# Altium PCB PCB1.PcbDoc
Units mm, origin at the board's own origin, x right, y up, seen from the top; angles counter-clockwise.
Board outline 68.2 x 35.94 mm, 2 copper layers (Top Layer, Bottom Layer); 89 components, 54 nets, 273 pads, 72 vias.
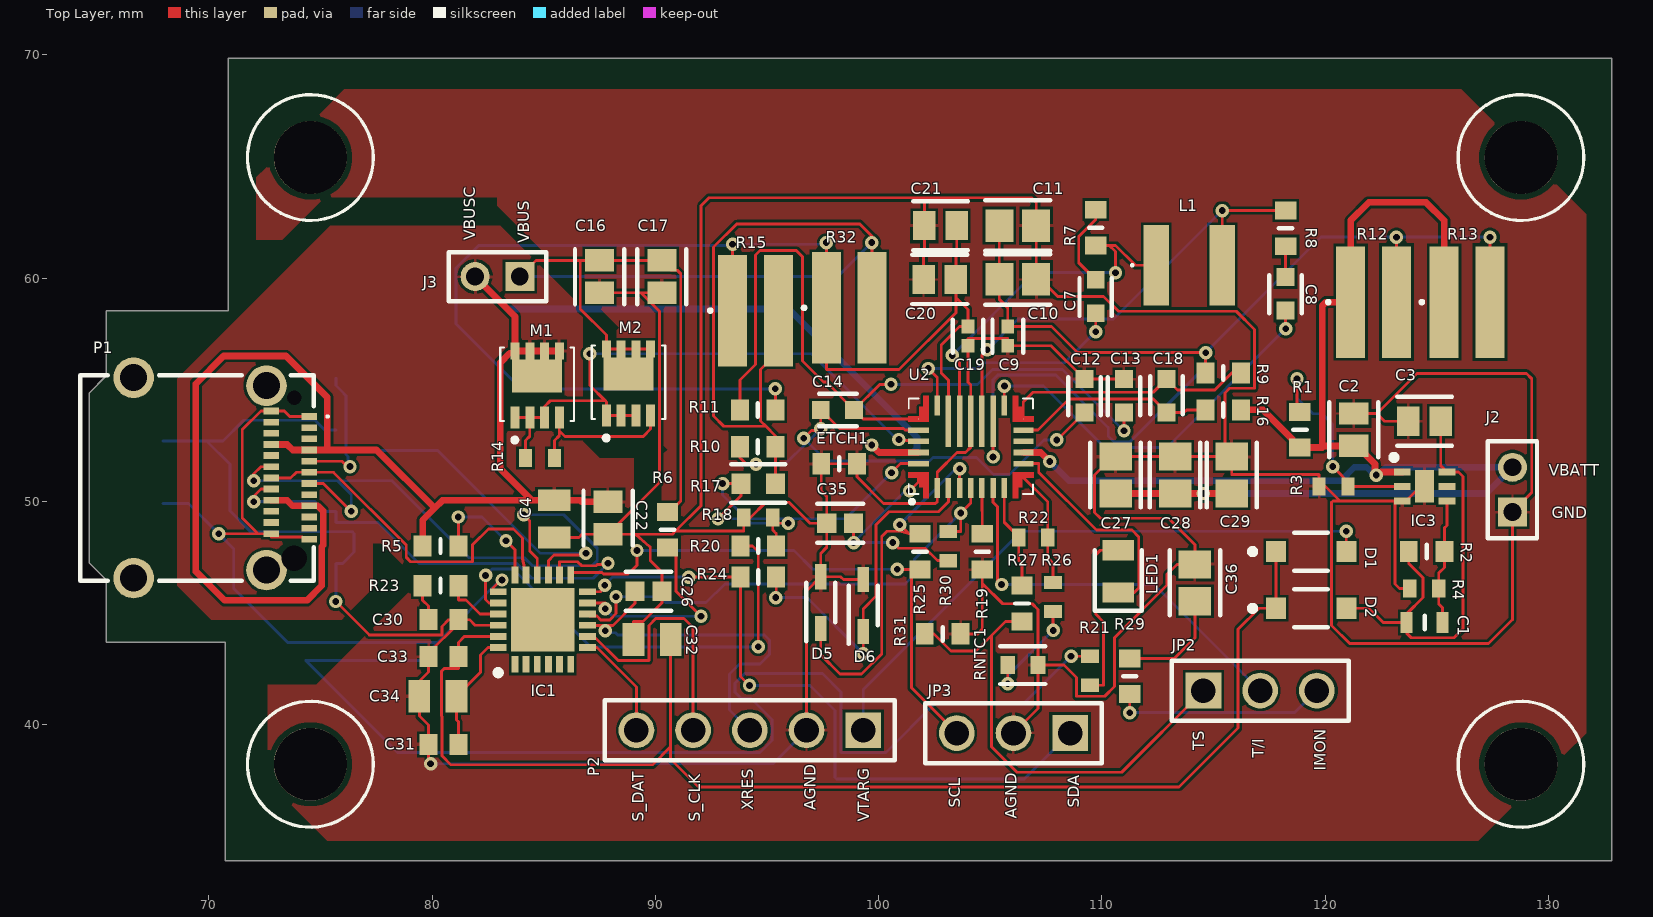
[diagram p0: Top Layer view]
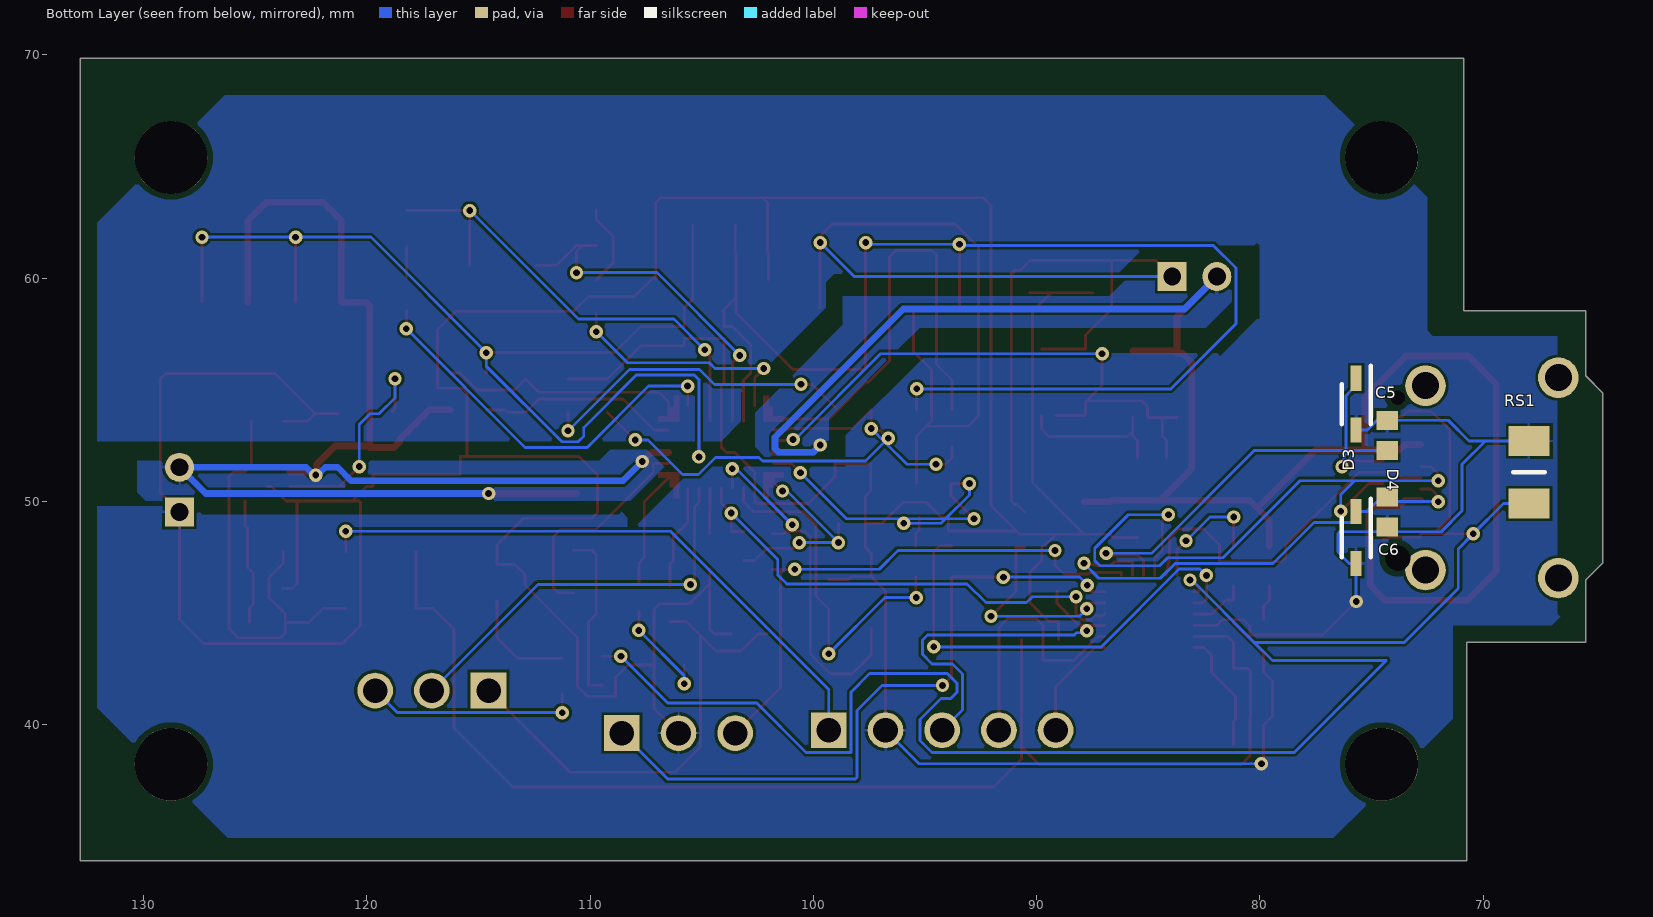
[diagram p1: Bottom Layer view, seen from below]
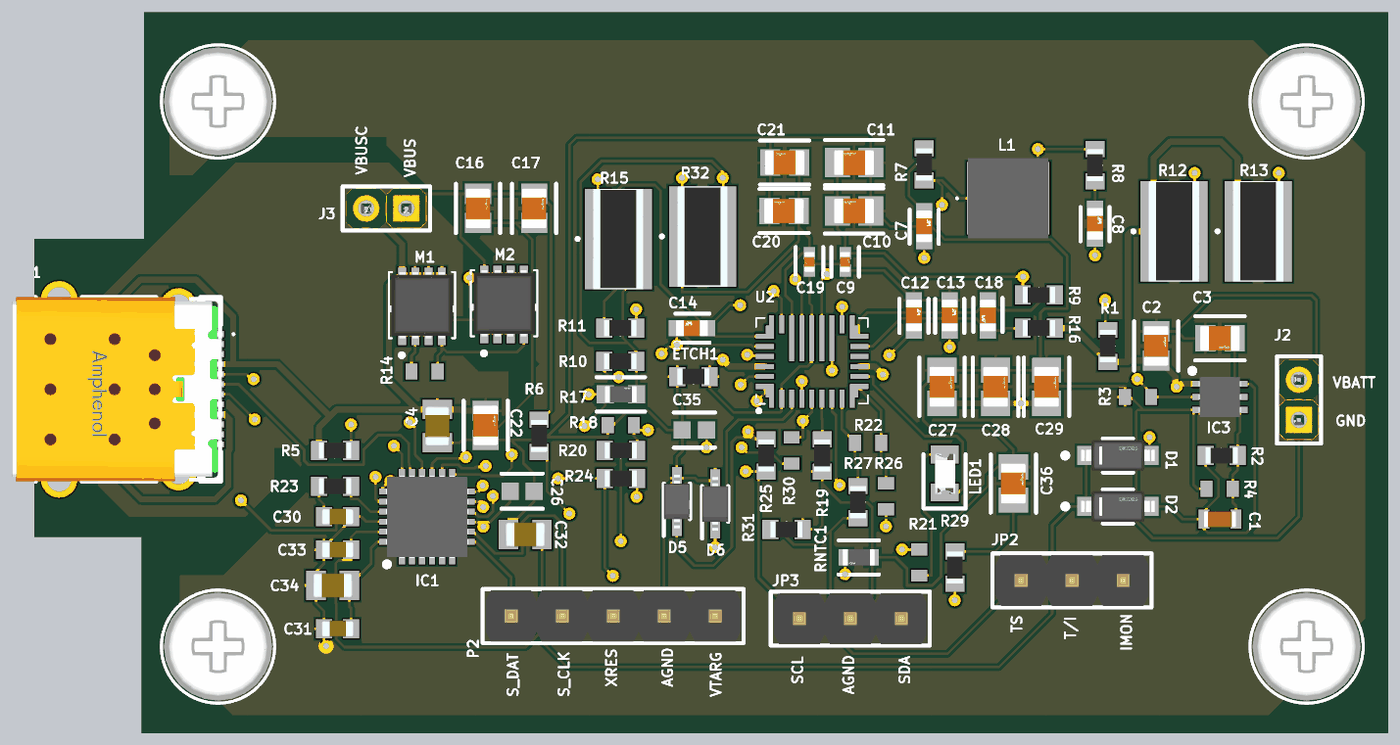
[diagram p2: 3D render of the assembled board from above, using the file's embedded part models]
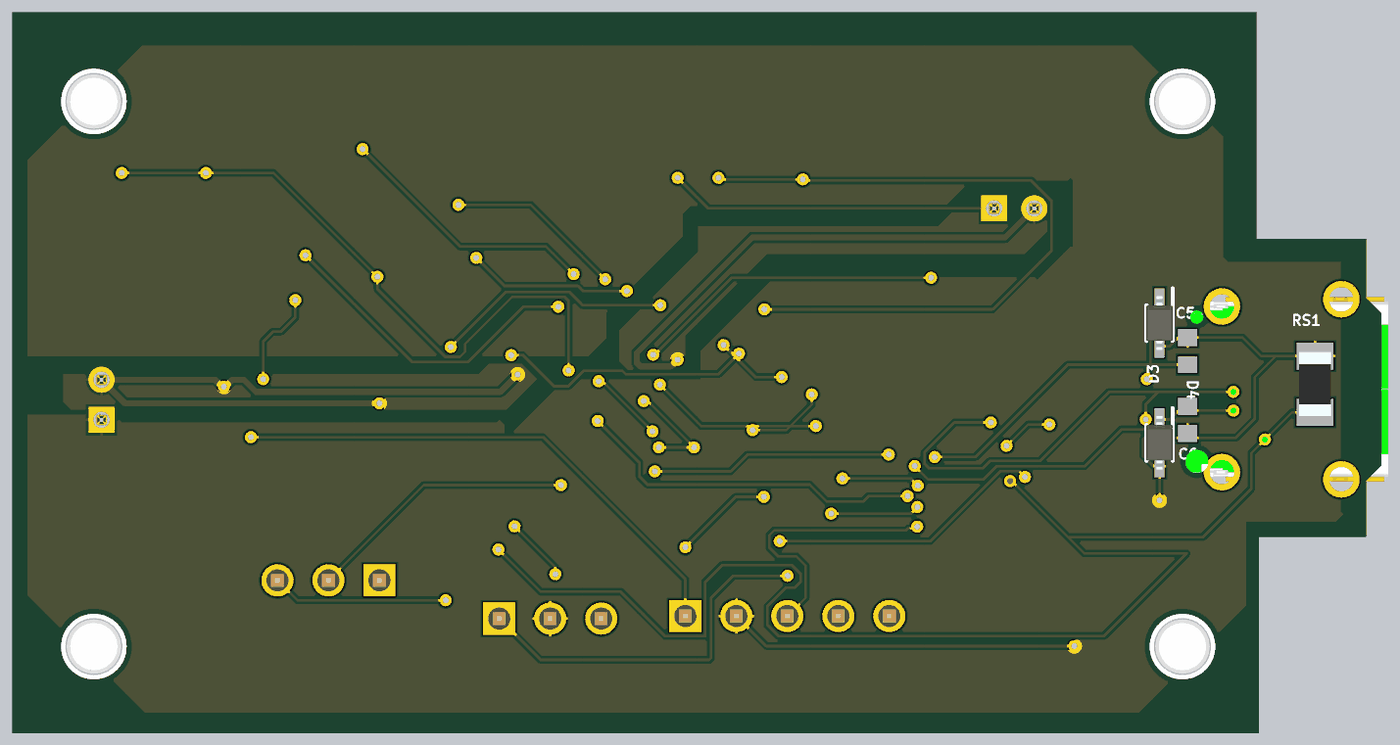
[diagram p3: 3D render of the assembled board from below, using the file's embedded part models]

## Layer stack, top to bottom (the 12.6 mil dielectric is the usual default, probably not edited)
Top Solder: solder mask 0.0102, Solder Resist, Dk 3.5
Top Layer: signal copper 0.035
Dielectric 1: dielectric 0.32, FR-4, Dk 4.8
Bottom Layer: signal copper 0.035
Bottom Solder: solder mask 0.0102, Solder Resist, Dk 3.5

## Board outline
64.643,47.244 65.405,46.482 65.405,43.688 70.739,43.688 70.739,33.909 132.842,33.909 132.842,69.85 70.866,69.85 70.866,58.547 65.405,58.547 65.405,55.626 64.643,54.864

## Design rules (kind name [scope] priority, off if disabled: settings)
BoardOutlineClearance [All] p1: gap=0.2 ignorepadtopadclearanceinfootprint=FALSE
Clearance [All] p1: gap=0.127 ignorepadtopadclearanceinfootprint=FALSE except(0.25: Arc-Hole Track-Hole SMDPad-Hole THPad-Hole Via-Hole Fill-Hole Poly-Hole Region-Hole Text-Hole)
ComponentClearance [All] p1: gap=0.127 collisioncheckmode=3 verticalgap=0.127 showdistances=TRUE
DiffPairsRouting [All] p1: maxlimit=0.254 minlimit=0.127 mostfreqgap=0.127 toplayer_minwidth=0.127 toplayer_maxwidth=25.4 toplayer_prefwidth=0.127 bottomlayer_minwidth=0.127 bottomlayer_maxwidth=25.4 bottomlayer_prefwidth=0.127 maxuncoupledlength=12.7
Height [All] p1: minheight=0 maxheight=1816.048 prefheight=12.7
HoleSize [All] p1: absolutevalues=TRUE maxlimit=6.3 minlimit=0.3 maxpercent=80.000 minpercent=20.000
HoleToHoleClearance [All] p1: gap=0.25 allowstackedmicrovias=FALSE
MinimumAnnularRing [All] p1: minimumring=0.076
MinimumSolderMaskSliver [All] p1: minsoldermaskwidth=0
PlaneClearance [All] p1: clearance=0.127
PlaneConnect PlaneConnectPowerPads [InPadClass('PowerPads')] p1: planeconnectstyle=Direct reliefexpansion=0.508 reliefentries=4 reliefconductorwidth=0.254 reliefairgap=0.254
PlaneConnect [All] p2: pad.planeconnectstyle=Relief pad.reliefexpansion=0.3 pad.reliefentries=4 pad.reliefconductorwidth=0.127 pad.reliefairgap=0.127 via.planeconnectstyle=Direct via.reliefexpansion=0.3 via.reliefentries=4 via.reliefconductorwidth=0.127 via.reliefairgap=0.127
PolygonConnect PolygonConnectPowerPads [All vs (InPadClass('PowerPads'))] p1: connectstyle=Direct reliefconductorwidth=0.254 reliefentries=4 polygonreliefangle="90 Angle" airgapwidth=0.254
PolygonConnect [All] p2: thpad.connectstyle=Relief thpad.reliefconductorwidth=0.127 thpad.reliefentries=4 thpad.polygonreliefangle="90 Angle" thpad.airgapwidth=0.127 smdpad.connectstyle=Relief smdpad.reliefconductorwidth=0.127 smdpad.reliefentries=4 smdpad.polygonreliefangle="90 Angle" smdpad.airgapwidth=0.127 via.connectstyle=Direct via.reliefconductorwidth=0.127 via.reliefentries=4 via.polygonreliefangle="90 Angle" via.airgapwidth=0.127
RoutingVias [All] p1: holewidth=0.3 width=0.6 viastyle="Through Hole" minholewidth=0.3 minwidth=0.6 maxholewidth=0.6 maxwidth=6.6
SilkToSilkClearance [All] p1: silktosilkclearance=0
SilkToSolderMaskClearance [IsPad] p1: minsilkscreentomaskgap=0.127 clearancetoexposedcopper=TRUE
SolderMaskExpansion [All] p1: expansion=0.075 istentingtop=FALSE
Width [All] p1: maxlimit=25.4 minlimit=0.127 preferedwidth=0.127 minimp=50.000000 maximp=50.000000 favimp=50.000000
20 further rules are at their usual default settings.

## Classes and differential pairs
component class Sheet5: C12 C13 C14 C16 C17 C19 C20 C21 C22 J3 M1 M2 R10 R11 R14 R15 R17 R32
component class Sheet4: C4 C5 C6 D3 D4 P1 R5 RS1
component class Sheet3: C7 C8 C9 C10 C11 C18 C27 C28 C29 C35 C36 D5 D6 ETCH1 J2 JP2 JP3 L1 LED1 R7 R8 R9 R12 R13 R16 R18 R19 R20 R21 R22 R24 R25 R26 R27 R29 R30 R31 RNTC1 U2
component class Sheet2: C1 C2 C3 D1 D2 IC3 R1 R2 R3 R4
component class Sheet1: C26 C30 C31 C32 C33 C34 IC1 P2 R6 R23

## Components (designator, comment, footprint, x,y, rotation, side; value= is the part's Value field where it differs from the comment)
C1 "C1608X7R1H102K080AE" CAPC1608X80N 124.46,44.577 r180 top
C2 "GRM21BR61E106KA73L" FP-GRM21B-0_15-IPC_C 121.285,53.213 r90 top
C3 "GRM21BR61E106KA73L" FP-GRM21B-0_15-IPC_C 124.46,53.594 r0 top
C4 "GRM21BR71A105KA01K" CAPC2012X145N 85.471,49.217 r270 top
C5 "GRM188R71H331KA01D" CAPC1608X90X35NL10T15 74.295,52.959 r270 bottom
C6 "GRM188R71H331KA01D" CAPC1608X90X35NL10T15 74.295,49.53 r90 bottom
C7 "885012206071" FP-885012206071-MFG 109.728,59.182 r90 top
C8 "885012206071" FP-885012206071-MFG 118.237,59.309 r90 top
C9 "GRM155R61E105KA12D" FP-GRM155-0_05-IPC_B 105.791,57.404 r90 top
C10 "GRM21BR61E226ME44L" FP-GRM21B-0_2-e0_2_0_7-IPC_B 106.235,59.944 r180 top
C11 "GRM21BR61E226ME44L" FP-GRM21B-0_2-e0_2_0_7-IPC_B 106.236,62.357 r180 top
C12 "NC" FP-885012206071-MFG 109.22,54.737 r90 top
C13 "NC" FP-885012206071-MFG 110.998,54.737 r90 top
C14 "885012206071" FP-885012206071-MFG 98.159,54.102 r180 top
C16 "GRM21BR61E106KA73L" FP-GRM21B-0_15-IPC_C 87.503,60.071 r90 top
C17 "GRM21BR61E106KA73L" FP-GRM21B-0_15-IPC_C 90.297,60.071 r90 top
C18 "885012206071" FP-885012206071-MFG 112.903,54.737 r270 top
C19 "GRM155R61E105KA12D" FP-GRM155-0_05-IPC_B 104.013,57.404 r270 top
C20 "GRM21BR61E106KA73L" FP-GRM21B-0_15-IPC_C 102.743,59.944 r180 top
C21 "GRM21BR61E106KA73L" FP-GRM21B-0_15-IPC_C 102.779,62.357 r180 top
C22 "GRM21BR61E106KA73L" FP-GRM21B-0_15-IPC_C 87.884,49.256 r90 top
C26 "GRM188R61E475KE11D" FP-GRM188-0_15-IPC_C 89.696,45.974 r180 top
C27 "GRM21BR61E226ME44L" FP-GRM21B-0_2-e0_2_0_7-IPC_B 110.617,51.181 r90 top
C28 "GRM21BR61E226ME44L" FP-GRM21B-0_2-e0_2_0_7-IPC_B 113.284,51.181 r90 top
C29 "NC" FP-GRM21B-0_2-e0_2_0_7-IPC_B 115.824,51.181 r90 top
C30 "885012206071" CAPC1608X87N 80.509,44.704 r0 top
C31 "885012206071" CAPC1608X87N 80.509,39.116 r180 top
C32 "GRM21BR71A105KA01K" CAPC2012X145N 89.857,43.815 r180 top
C33 "885012206071" CAPC1608X87N 80.509,43.053 r0 top
C34 "GRM21BR71A105KA01K" CAPC2012X145N 80.264,41.275 r0 top
C35 "GRM188R61E475KE11D" FP-GRM188-0_15-IPC_C 98.28,49.022 r180 top
C36 "NC" FP-GRM21B-0_2-e0_2_0_7-IPC_B 114.173,46.355 r90 top
D1 "B0520LW-7-F" FP-SOD123-MFG 119.38,47.752 r0 top value=170pF
D2 "B0520LW-7-F" FP-SOD123-MFG 119.38,45.212 r0 top value=170pF
D3 "VLIN1626-02GHE3-18" SOD2713X115N 75.692,54.356 r270 bottom
D4 "VLIN1626-02GHE3-18" SOD2713X115N 75.692,48.387 r270 bottom
D5 "VLIN1626-02GHE3-18" SOD2713X115N 97.409,45.466 r90 top
D6 "VLIN1626-02GHE3-18" SOD2713X115N 99.314,45.339 r90 top
ETCH1 "RC0603JR-070RL" RESC1608X55N 98.234,51.689 r180 top
IC1 "CYPD3171-24LQXQT" QFN50P400X400X60-25N-D 84.963,44.704 r90 top
IC3 "MP2013AGG-Z" SON65P200X200X100-7N-D 124.46,50.673 r0 top
J2 "M22-2510205" FP-M22-2510205-MFG 128.397,50.53 r90 top
J3 "M22-2510205" FP-M22-2510205-MFG 82.931,60.071 r180 top
JP2 "61300311121" 61300311121 117.094,41.529 r0 top
JP3 "61300311121" 61300311121 106.045,39.624 r180 top
L1 "MPL-SE4030-2R2" MPLSE40302R2 113.919,60.579 r0 top
LED1 "150080VS75000" LEDC2012X80N 110.744,46.863 r90 top
M1 "SISA14DN-T1-GE3" SQ7414AENT1GE3 84.709,54.776 r90 top
M2 "SISA14DN-T1-GE3" SQ7414AENT1GE3 88.799,54.866 r90 top
MP1 "9901" FP-9901-MFG 128.778,65.405 r0 top
MP2 "9901" FP-9901-MFG 128.778,38.227 r0 top
MP3 "9901" FP-9901-MFG 74.549,65.405 r0 top
MP4 "9901" FP-9901-MFG 74.549,38.227 r0 top
P1 "12401598E4#2A" 12401598E42A 69.469,51.054 r270 top
P2 "61300511121" 61300511121 94.234,39.751 r180 top
R1 "RC0603JR-070RL" RESC1608X55N 118.872,53.213 r90 top
R2 "RC0603JR-072ML" RESC1608X55N 124.549,47.752 r180 top
R3 "RC0603JR-075K1L" RESC1608X55X25LL10T15 120.381,50.673 r0 top
R4 "RC0603FR-071ML" RESC1608X55X25LL10T15 124.445,46.101 r0 top
R5 "RC0603JR-070RL" RESC1608X55N 80.379,48.006 r180 top
R6 "RC0603JR-070RL" RESC1608X55N 90.551,48.73 r270 top
R7 "RC0603JR-070RL" RESC1608X55N 109.728,62.268 r90 top
R8 "RC0603JR-070RL" RESC1608X55N 118.237,62.23 r270 top
R9 "SFR03EZPJ2R0" RESC1608X55N 115.443,55.753 r0 top
R10 "SFR03EZPJ2R0" RESC1608X55N 94.588,52.451 r180 top
R11 "SFR03EZPJ2R0" RESC1608X55N 94.588,54.102 r180 top
R12 "ERJ-C1CFR02U" ERJC1 122.174,58.928 r0 top
R13 "ERJ-C1CFR02U" ERJC1 126.365,58.928 r0 top
R14 "RC0603FR-071ML" RESC1608X55X25LL10T15 84.836,51.943 r0 top
R15 "ERJ-C1CFR02U" ERJC1 94.488,58.547 r0 top
R16 "SFR03EZPJ2R0" RESC1608X55N 115.443,54.102 r180 top
R17 "RC0603FR-07200KL" FP-RC0603-0_55-IPC_B 94.615,50.8 r0 top
R18 "RC0603FR-0713KL" RESC1608X55X25LL10T15 94.615,49.276 r0 top
R19 "RC0603JR-070RL" RESC1608X55N 104.648,47.752 r90 top
R20 "RC0603JR-070RL" RESC1608X55N 94.615,48.006 r0 top
R21 "RC0603FR-072KL" RESC1608X55X25LL10T15 109.474,42.418 r270 top
R22 "RC0603FR-0715KL" RESC1608X55X25LL10T15 106.934,48.387 r0 top
R23 "RC0603JR-070RL" RESC1608X55N 80.379,46.228 r180 top
R24 "SFR03EZPJ2R0" RESC1608X55N 94.615,46.609 r0 top
R25 "SFR03EZPJ2R0" RESC1608X55N 101.854,47.752 r90 top
R26 "RC0603JR-075K1L" RESC1608X55X25LL10T15 107.823,45.72 r90 top
R27 "RC0603JR-07100KL" RESC1608X55N 106.426,45.428 r90 top
R29 "RC0603JR-070RL" RESC1608X55N 111.252,42.168 r90 top
R30 "RC0603JR-075K1L" RESC1608X55X25LL10T15 103.124,48.002 r90 top
R31 "RC0603JR-07100KL" RESC1608X55N 102.87,44.069 r180 top
R32 "ERJ-C1CFR02U" ERJC1 98.688,58.674 r0 top
RNTC1 "RC0603FR-0710KL" FP-RC0603-0_55-IPC_C 106.468,42.672 r180 top
RS1 "PA1206FRF070R005L" RESC3216X65N 67.945,51.308 r90 bottom
U2 "MP2651" MP2651 103.977,52.434 r90 top

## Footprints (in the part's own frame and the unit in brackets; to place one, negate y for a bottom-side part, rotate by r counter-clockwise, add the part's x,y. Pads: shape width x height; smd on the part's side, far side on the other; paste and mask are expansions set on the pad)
12401598E42A [mm]
  rect 0.3x0.7 smd: A1(-2.75,5.025) A2(-2.25,5.025) A3(-1.75,5.025) A4(-1.25,5.025) A5(-0.75,5.025) A6(-0.25,5.025) A7(0.25,5.025) A8(0.75,5.025) A9(1.25,5.025) A10(1.75,5.025) A11(2.25,5.025) A12(2.75,5.025) B1(2.5,3.325) B2(2,3.325) B3(1.5,3.325) B4(1,3.325) B5(0.5,3.325) B6(0,3.325) B7(-0.5,3.325) B8(-1,3.325) B9(-1.5,3.325) B10(-2,3.325) B11(-2.5,3.325) B12(-3,3.325)
  round 1.815 hole 1.21: MH1(-4.13,3.115) MH2(4.13,3.115) MH3(4.49,-2.835) MH4(-4.49,-2.835)
  round 0.325 hole 0.65 unplated: MH5(-3.6,4.365)
  round 0.575 hole 1.15 unplated: MH6(3.6,4.365)
  silkscreen extent -4.6,-5.22 4.6,5.9, body extent -4.6,-5.17 4.6,5.32, height 3.3
61300311121 [mm] "Pin Header, pitch 2.54 mm, THT, Vertical, single row, 3p"
  rect 1.6x1.6 hole 1.1: 1(-2.54,0)
  round 1.6 hole 1.1: 2(0,0) 3(2.54,0)
  silkscreen extent -3.96,-1.34 3.96,1.34, body extent -3.81,-1.27 3.81,1.27, height 8.57
61300511121 [mm] "Pin Header, pitch 2.54 mm, THT, Vertical, single row, 5p"
  rect 1.6x1.6 hole 1.1: 1(-5.08,0)
  round 1.6 hole 1.1: 2(-2.54,0) 3(0,0) 4(2.54,0) 5(5.08,0)
  silkscreen extent -6.5,-1.34 6.5,1.34, body extent -6.35,-1.27 6.35,1.27, height 8.57
CAPC1608X80N [mm]
  rect 0.54x0.94 smd: 1(-0.8,0) 2(0.8,0)
  silkscreen extent 0,-0.3 0,0.3, body extent -0.8,-0.4 0.8,0.4, height 0.8
CAPC1608X87N [mm]
  rect 0.8x0.94 smd: 1(-0.67,0) 2(0.67,0)
  body extent -0.8,-0.4 0.8,0.4, height 0.87
CAPC1608X90X35NL10T15 [mm] "Chip Capacitor, 2-Leads, Body 1.60x0.80mm, IPC Medium Density"
  rect 0.85x0.95 smd: 1(-0.675,0) 2(0.675,0)
  body extent -0.85,-0.45 0.85,0.45, height 0.9
CAPC2012X145N [mm]
  rect 0.97x1.47 smd: 1(-0.83,0) 2(0.83,0)
  body extent -1,-0.63 1,0.63, height 1.45
ERJC1 [mm]
  rect 1.3x5 smd: 1(-1.025,0) 2(1.025,0)
  silkscreen extent -2.07,-0.05 -1.97,0.05, body extent -1.25,-2.5 1.25,2.5, height 0.55
FP-9901-MFG [mil]
  round 128.5 hole 128.5 unplated paste-39370.1 mask+0: ""(0,0)
  silkscreen extent -111,-111 111,111, body extent -115,-115 115,115, height 10
FP-885012206071-MFG [mm]
  rect 0.8x0.8 smd paste+0 mask+0: 1(-0.75,0) 2(0.75,0)
  silkscreen extent -0.87,-0.73 0.82,0.73, body extent -1.25,-0.55 1.25,0.55, height 0.25
FP-GRM21B-0_2-e0_2_0_7-IPC_B [mm]
  rect 1.255x1.456 smd paste+0 mask+0: 1(-0.826,0) 2(0.826,0)
  silkscreen extent -1.45,-1.13 1.45,1.13, body extent -1.7,-0.98 1.7,0.98, height 0.25
FP-GRM21B-0_15-IPC_C [mm]
  rect 1.006x1.308 smd paste+0 mask+0: 1(-0.726,0) 2(0.726,0)
  silkscreen extent -1.23,-1.1 1.23,1.1, body extent -1.33,-0.8 1.33,0.8, height 0.25
FP-GRM155-0_05-IPC_B [mm]
  rect 0.615x0.572 smd paste+0 mask+0: 1(-0.429,0) 2(0.429,0)
  silkscreen extent -0.74,-0.69 0.74,0.69, body extent -0.89,-0.44 0.89,0.44, height 0.25
FP-GRM188-0_15-IPC_C [mm]
  rect 0.856x0.858 smd paste+0 mask+0: 1(-0.601,0) 2(0.601,0)
  silkscreen extent -1.03,-0.87 1.03,0.87
FP-M22-2510205-MFG [mm]
  rect 1.3x1.3 hole 0.8 paste-1000 mask+0: 1(-1,0)
  round 1.3 hole 0.8 paste-1000 mask+0: 2(1,0)
  silkscreen extent -2.18,-1.1 2.17,1.1, body extent -2.27,-1.2 2.27,1.2, height 0.25
FP-RC0603-0_55-IPC_B [mm]
  rect 0.859x0.912 smd paste+0 mask+0: 1(-0.777,0) 2(0.777,0)
  silkscreen extent -1.21,-0.86 1.21,0.86, body extent -1.46,-0.71 1.46,0.71, height 0.25
FP-RC0603-0_55-IPC_C [mm]
  rect 0.659x0.812 smd paste+0 mask+0: 1(-0.677,0) 2(0.677,0)
  silkscreen extent -1.01,-0.85 1.01,0.85, body extent -1.11,-0.55 1.11,0.55, height 0.25
FP-SOD123-MFG [mm]
  rect 0.9x0.95 smd paste+0 mask+0: 1(-1.575,0) 2(1.575,0)
  silkscreen extent -2.75,-0.85 0.75,0.85, body extent -2.12,-0.95 2.12,0.95, height 0.25
LEDC2012X80N [mm]
  rect 0.9x1.4 smd: 1(-0.95,0) 2(0.95,0)
  silkscreen extent -1.75,-1.05 0.95,1.05, body extent -1.03,-0.53 0.97,0.47, height 0.82
MP2651 [mm] "MP2651 – BUCK-BOOST CHARGER FOR 1 TO 4 CELLS IN SERIES"
  round 0.025 smd: 1(-1.24,2.184) 9(-1.24,-2.504) 15(1.26,-2.504) 24(1.26,2.183)
  rect 0.9x0.25 smd: 2(-1.84,1.345) 3(-1.84,0.845) 4(-1.84,0.345) 5(-1.84,-0.155) 6(-1.84,-0.655) 7(-1.84,-1.155) 8(-1.84,-1.655) 17(1.86,-1.655) 23(1.86,1.345)
  rect 0.25x0.9 smd: 11(-0.74,-2.517) 12(-0.24,-2.517) 13(0.26,-2.517) 14(0.76,-2.517)
  rect 2.3x0.25 smd: 18(1.16,-1.155) 19(1.16,-0.655) 20(1.16,-0.155) 21(1.16,0.345) 22(1.16,0.845)
  rect 0.25x0.925 smd: 26(0.76,2.183) 27(0.26,2.183) 28(-0.24,2.183) 29(-0.74,2.183)
  Top Layer region: -1.115,-2.042 -1.115,-2.967 -1.365,-2.967 -1.365,-2.467 -1.79,-2.467 -1.79,-2.292 -2.29,-2.292 -2.29,-2.042
  Top Layer region: 2.31,-2.042 2.31,-2.292 1.81,-2.292 1.81,-2.467 1.385,-2.467 1.385,-2.967 1.135,-2.967 1.135,-2.042
  Top Layer region: -2.29,1.721 -2.29,1.971 -1.79,1.971 -1.79,2.146 -1.365,2.146 -1.365,2.646 -1.115,2.646 -1.115,1.721
  Top Layer region: 1.135,1.721 1.135,2.646 1.385,2.646 1.385,2.146 1.81,2.146 1.81,1.971 2.31,1.971 2.31,1.721
  silkscreen extent -2.5,-2.94 2.17,2.63
MPLSE40302R2 [mm]
  rect 1.15x3.6 smd: 1(-1.475,0) 2(1.475,0)
  silkscreen extent -2.6,-0.05 -2.5,0.05, body extent -2,-2 2,2, height 3.1
QFN50P400X400X60-25N-D [mm]
  rect 0.75x0.3 smd: 1(-2,1.25) 2(-2,0.75) 3(-2,0.25) 4(-2,-0.25) 5(-2,-0.75) 6(-2,-1.25) 13(2,-1.25) 14(2,-0.75) 15(2,-0.25) 16(2,0.25) 17(2,0.75) 18(2,1.25)
  rect 0.3x0.75 smd: 7(-1.25,-2) 8(-0.75,-2) 9(-0.25,-2) 10(0.25,-2) 11(0.75,-2) 12(1.25,-2) 19(1.25,2) 20(0.75,2) 21(0.25,2) 22(-0.25,2) 23(-0.75,2) 24(-1.25,2)
  rect 2.85x2.85 smd: 25(0,0)
  silkscreen extent -2.5,1.88 -2.25,2.12, body extent -2.05,-2.05 2.05,2.05, height 0.6
RESC1608X55N [mm]
  rect 0.8x0.95 smd: 1(-0.8,0) 2(0.8,0)
  silkscreen extent 0,-0.3 0,0.3, body extent -0.8,-0.4 0.8,0.4, height 0.55
RESC1608X55X25LL10T15 [mm] "Chip Resistor, 2-Leads, Body 1.60x0.80mm, IPC High Density"
  rect 0.6x0.8 smd: 1(-0.65,0) 2(0.65,0)
  body extent -0.85,-0.45 0.85,0.45, height 0.55
RESC3216X65N [mm]
  rect 1.35x1.85 smd: 1(-1.4,0) 2(1.4,0)
  silkscreen extent 0,-0.7 0,0.7, body extent -1.6,-0.8 1.6,0.8, height 0.65
SOD2713X115N [mm]
  rect 1.125x0.5 smd: 1(-1.162,0) 2(1.162,0)
  silkscreen extent -1.73,-0.65 0.89,0.65, body extent -1.34,-0.65 1.34,0.65, height 1.15
SON65P200X200X100-7N-D [mm]
  rect 0.75x0.3 smd: 1(-1,0.65) 2(-1,0) 3(-1,-0.65) 4(1,-0.65) 5(1,0) 6(1,0.65)
  rect 0.85x1.45 smd: 7(0,0)
  silkscreen extent -1.5,1.18 -1.25,1.42, body extent -1.05,-1 1.05,1, height 1
SQ7414AENT1GE3 [mm]
  rect 0.99x0.405 smd: 1(-1.018,0.99) 2(-1.018,0.33) 3(-1.018,-0.33) 4(-1.018,-0.99)
  rect 0.76x0.405 smd: 5(1.967,-0.99) 6(1.967,-0.33) 7(1.967,0.33) 8(1.967,0.99)
  rect 1.475x2.235 smd: 9(0.85,0)
  silkscreen extent -2.12,-1.65 2.12,1.65, body extent -1.18,-1.65 2.12,1.65, height 1.06

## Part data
C1: "Capacitor", Manufacturer_Name=TDK, Mouser Part Number=810-C1608X7R1H102KAE
C2 C3 C16 C17 C20 C21 C22: library part CMP-2007-03541-2, "Chip Multilayer Ceramic Capacitors for General Purpose, 0805, 10uF, X5R, 15%, 10%, 25V", Capacitance=10uF, Case Code (Imperial)=0805, Case Code (Metric)=2012, Dielectric=X5R, Max Operating Temperature=85°C, Min Operating Temperature=-55°C, Package Quantity=1, Tolerance=10%, Voltage=25V
C4 C32 C34: "Capacitor", Manufacturer_Name="Murata Electronics", Mouser Part Number=81-GRM40X105K10K
C5 C6: library part CMP-2006-02914-1, Manufacturer=Murata
C7 C8 C12 C13 C14 C18: library part CMP-207839-000033-1, "CAP CER 0.1UF 25V X7R 0603", Capacitance=100nF, Case Code (Imperial)=0603, Case Code (Metric)=1608, Dielectric=X7R, Max Operating Temperature=125°C, Min Operating Temperature=-55°C, Tolerance=10%, Voltage Rating=25V
C9 C19: library part CMP-2008-04581-2, "Chip Multilayer Ceramic Capacitors for General Purpose, 0402, 1.0uF, X5R, 15%, 10%, 25V", Capacitance=1uF, Case Code (Imperial)=0402, Case Code (Metric)=1005, Dielectric=X5R, Max Operating Temperature=85°C, Min Operating Temperature=-55°C, Package Quantity=10000, Tolerance=10%, Voltage=25V
C10 C11 C27 C28 C29 C36: library part CMP-2007-03222-3, "Chip Multilayer Ceramic Capacitors for General Purpose, 0805, 22uF, X5R, 15%, 20%, 25V", Capacitance=22uF, Case Code (Imperial)=0805, Case Code (Metric)=2012, Dielectric=X5R, Max Operating Temperature=85°C, Min Operating Temperature=-55°C, Package Quantity=3000, Resistor Type=Ceramic, Tolerance=20%, Voltage=25V
C26 C35: library part CMP-2006-02523-2, "Chip Multilayer Ceramic Capacitors for General Purpose, 0603, 4.7uF, X5R, 15%, 10%, 25V", Capacitance=4.7uF, Case Code (Imperial)=0603, Case Code (Metric)=1608, Dielectric=X5R, Max Operating Temperature=85°C, Min Operating Temperature=-55°C, Package Quantity=4000, Tolerance=10%, Voltage=25V
C30 C31 C33: "Capacitor", Manufacturer_Name="Wurth Elektronik", Mouser Part Number=710-885012206071
D1 D2: library part CMP-12790-000026-1, "DIODE SCHOTTKY 20V 500MA SOD123", Capacitance=170pF, Forward Current=0.5A, Manufacturer="Diodes Inc.", Max Junction Temp=+125°C, Max Repetitive Reverse Voltage=20V, Max Surge Forward Current=5.5A, Package=SOD123, Peak Reverse Current=250uA, Temperature="-65°C to +125°C", Temperature Range Low=-65°C
D3 D4 D5 D6: "Diode ESD (Bi-directional)", Manufacturer_Name=Vishay, Mouser Part Number=78-VLIN1626-02GHE318
ETCH1 R1 R5 R6 R7 R8 R19 R20 R23 R29: "Resistor", Manufacturer_Name=YAGEO, Mouser Part Number=603-RC0603JR-070RL
IC1: "Integrated Circuit", Manufacturer_Name="Cypress Semiconductor", Mouser Part Number=727-CYPD3171-24LQXQT
IC3: "Integrated Circuit", Manufacturer_Name="Monolithic Power Systems (MPS)", Mouser Part Number=946-MP2013AGG-Z
J2 J3: library part CMP-15831-000005-1, "CONN HEADER VERT 2POS 2MM", Current Rating=2A, Manufacturer=Harwin, Package=0, Temperature="-40°C to +105°C", Temperature Range High=+105°C, Temperature Range Low=-40°C
JP2 JP3: library part CMP-1502-01062-1, "THT Vertical Pin Header WR-PHD, Pitch 2.54 mm, Single Row, 3 pins", Contact Resistance=20mOhm, Manufacturer="Wurth Elektronik", Operating Temperature=-40to105degC, Rated Current=3A, Withstanding Voltage=500VAC, Working Voltage=250VAC
L1: "Inductor", Manufacturer_Name="Monolithic Power Systems (MPS)", Mouser Part Number=946-MPL-SE4030-2R2
LED1: "LED", Manufacturer_Name="Wurth Elektronik", Mouser Part Number=710-150080VS75000
M1 M2: "MOSFET (N-Channel)", Manufacturer_Name=Vishay, Mouser Part Number=78-SISA14DN-T1-GE3
MP1 MP2 MP3 MP4: library part CMP-19664-000002-1, "MACHINE SCREW PAN PHILLIPS 4-40", Package Quantity=100
P1: "Connector", Manufacturer_Name="Amphenol Communications Solutions", Mouser Part Number=523-12401598E4#2A
P2: library part CMP-1502-01068-1, "THT Vertical Pin Header WR-PHD, Pitch 2.54 mm, Single Row, 5 pins", Contact Resistance=20mOhm, Manufacturer="Wurth Elektronik", Operating Temperature=-40to105degC, Rated Current=3A, Withstanding Voltage=500VAC, Working Voltage=250VAC
R2 RS1: "Resistor", Manufacturer_Name=YAGEO
R3 R26 R30: library part CMP-1012-00091-2, "Chip Resistor, 5.1 KOhm, +/- 5%, 0.1 W, -55 to 155 degC, 0603 (1608 Metric), RoHS, Tape and Reel", Case Code - in=0603, Case Code - mm=1608, Manufacturer=Yageo, Operating Temperature Range=-55Cto+155C, Package Description="2-Pin Surface Mount Device, Body 1.6 x 0.8 mm", Power Rating=100mW, Resistance=5.1kOhms, Temperature Coefficient=100PPM/C, Tolerance=5%, Voltage Rating=50V
R4 R14: library part CMP-1659-00056-1, "Chip Resistor, 1 MOhm, +/- 1%, 100 mW, -55 to 155 degC, 0603 (1608 Metric), RoHS, Tape and Reel", Capacitance="1 mF", Case\Package=Radial, Max Operating Temperature="85 degC", Min Operating Temperature="-40 degC", Package Quantity=200, Tolerance=20%, Voltage Rating="25 V"
R9 R10 R11 R16 R24 R25: "Resistor", Manufacturer_Name="ROHM Semiconductor"
R12 R13 R15 R32: "Resistor", Manufacturer_Name=Panasonic, Mouser Part Number=667-ERJ-C1CFR02U
R17: library part CMP-03412-037786-1, "RES SMD 200K OHM 1% 1/10W 0603", Case Code (Imperial)=0603, Case Code (Metric)=1608, Max Operating Temperature=155°C, Max Power Dissipation=100mW, Min Operating Temperature=-55°C, Package Quantity=1, Resistance=200kR, Resistance Tolerance=1%, Resistor Type="Thick Film", Temperature Coefficient=100ppm/°C, Voltage Rating=50V
R18: library part CMP-2000-06927-1, "Chip Resistor, 13 KOhm, +/- 1%, 0.1 W, -55 to 155 degC, 0603 (1608 Metric), RoHS, Tape and Reel", Case Code - in=0603, Case Code - mm=1608, Manufacturer=Yageo, Operating Temperature Range=-55Cto+155C, Package Description="2-Pin Surface Mount Device, Body 1.6 x 0.8 mm", Power Rating=100mW, Resistance=13kOhms, Temperature Coefficient=100PPM/C, Tolerance=1%, Voltage Rating=50V
R21: library part CMP-2000-06937-1, "Chip Resistor, 2 KOhm, +/- 1%, 50 V, -55 to 155 degC, 0603 (1608 Metric), RoHS, Tape and Reel", Manufacturer=Yageo, Operating Temperature=-55°C~155°C, Package / Case=0603(1608Metric), Package Description="2-Pin Surface Mount Device, Body 1.6 x 0.8 mm", Package Reference=0603, Power (Watts)=0.1W,1/10W, Resistance (Ohms)=2k, Standard Package=1, Temperature Coefficient=±100ppm/°C, Tolerance=±1%
R22: library part CMP-1659-00032-1, "Chip Resistor, 15 KOhm, +/- 1%, 0.1 W, -55 to 155 degC, 0603 (1608 Metric), RoHS, Tape and Reel"
R27 R31: "Resistor", Manufacturer_Name=YAGEO, Mouser Part Number=603-RC0603JR-07100KL
RNTC1: library part CMP-2100-03664-2, "RES 10K OHM 1% 1/10W 0603", Case Code (Imperial)=0603, Case Code (Metric)=1608, Max Operating Temperature=155°C, Max Power Dissipation=100mW, Min Operating Temperature=-55°C, Resistance=10kR, Resistance Tolerance=1%, Resistor Type="Thick Film", Temperature Coefficient=100ppm/°C, Voltage Rating=75V, Voltage Rating (DC)=50V
U2: "MP2651 – BUCK-BOOST CHARGER FOR 1 TO 4 CELLS IN SERIES"

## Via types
v1: diameter 0.6, hole 0.3, Top Layer to Bottom Layer, 72 vias

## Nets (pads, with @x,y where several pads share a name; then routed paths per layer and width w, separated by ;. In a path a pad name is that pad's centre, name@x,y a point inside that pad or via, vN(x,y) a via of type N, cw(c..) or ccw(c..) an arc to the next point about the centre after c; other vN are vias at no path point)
ACOK: LED1.1 U2.11 | length 10
  Top Layer w0.127: U2.11 107.18,51.694 107.18,51.3 109.763,48.717 111.354,48.717 111.658,48.412 111.658,46.126 111.445,45.913 LED1.1
ADDR: R19.2 U2.6 | length 2
  Top Layer w0.127: U2.6 104.632,49.572 104.648,49.555 R19.2
AGND: C2.2 C3.1 C4.2 C5.1 C6.1 C9.1 C10.1 C11.1 C12.2 C13.2 C16.1 C17.1 C19.2 C20.2 C21.2 C22.1 C26.1 C27.2 C28.2 C29.2 C30.2 C31.2 C32.2 C33.1 C34.1 C35.2 C36.2 D3.2 D4.2 D5.2 D6.2 ETCH1.1 ETCH1.2 IC1.22 IC3.3 IC3.7 J2.1 JP3.2 P2.2 R3.1 R4.1 R18.1 R19.1 R31.1 RNTC1.1 RS1.2 U2.2 U2.20 | length 271.5
  Top Layer w0.127: v1(75.692,45.517) 77.191,44.018 80.442,44.018 80.442,44.399 80.747,44.704 C30.2 ; v1(79.934,38.252) 79.839,38.347 C31.2 79.839,39.98 79.434,40.385 C34.1 79.434,41.961 79.839,42.366 C33.1 79.839,43.205 81.179,44.545 C30.2 ; IC1.22 81.92,44.454 81.67,44.704 C30.2 ; C4.2 86.589,48.387 86.731,48.53 C22.1 ; C16.1 88.9,59.345 89.372,59.345 ; C32.2 89.027,44.616 89.453,44.616 90.297,45.46 C26.1 90.297,46.83 89.771,47.356 89.771,47.955 89.122,48.53 ; C17.1 89.372,59.345 ; P2.2 96.774,45.993 D5.2 ; D6.2 98.425,46.501 98.298,46.628 D5.2 ; C20.2 102.017,61.112 102.053,61.148 C21.2 102.053,63.398 102.256,63.602 ; R31.1 104.445,44.069 104.648,44.272 104.648,46.33 ; R19.1 104.648,46.33 ; JP3.2 107.144,40.723 RNTC1.1 ; C10.1 C10.1@107.062,60.147 ; C13.2 C12.2 107.732,56.975 C9.1 105.791,57.301 104.013,57.301 C19.2 104.013,55.338 104.132,55.22 U2.20 104.132,52.426 103.903,52.197 103.521,52.197 102.632,51.308 102.632,49.985 102.558,49.911 100.228,49.911 99.034,51.105 ETCH1.1 ETCH1.2 97.434,50.461 97.679,50.216 C35.2 ; C2.2 122.326,53.939 ; C3.1 122.672,53.594 122.326,53.939 ; R4.1 123.342,46.101 123.139,46.304 IC3.3@123.139,50.023 ; IC3.7 124.272,50.673 123.622,50.023 IC3.3 IC3.3@123.139,50.023 ; C22.1 89.122,48.53 ; C22.1 90.195,50.841 90.195,58.522 89.372,59.345 ; 89.122,48.53 90.77,48.53 90.912,48.672 ; 90.912,48.672 92.05,49.809 92.05,63.246 92.405,63.602 102.256,63.602 ; 90.912,48.672 93.965,48.672 R18.1 94.259,49.276 94.945,49.962 95.987,49.962 96.926,49.022 C35.2 ; D5.2 97.409,47.676 97.679,47.946 C35.2 ; 102.256,63.602 106.858,63.602 107.062,63.398 C11.1 107.062,61.138 C10.1@107.062,60.147 ; 104.648,46.33 105.562,45.415 106.883,45.415 107.144,45.154 RNTC1.1 ; C10.1@107.062,60.147 108.027,59.182 110.084,59.182 110.744,58.522 116.027,58.522 116.84,57.709 116.84,55.067 115.722,55.067 115.519,54.864 C29.2@115.519,52.007 ; RNTC1.1 108.306,42.672 108.864,42.113 108.864,41.275 110.134,41.275 110.566,41.707 110.566,43.891 112.928,46.253 112.928,46.736 113.373,47.181 C36.2 114.173,48.057 112.979,49.251 109.931,49.251 109.677,49.505 109.677,51.181 110.503,52.007 C27.2 111.938,52.007 C28.2 C29.2@115.519,52.007 ; C29.2@115.519,52.007 C29.2 115.824,51.206 119.731,51.206 R3.1 120.015,50.673 120.665,50.023 ; 120.665,50.023 IC3.3@123.139,50.023 ; 120.665,50.023 120.356,50.023 120.294,49.962 120.294,44.45 121.107,43.637 127.33,43.637 128.397,44.704 J2.1 129.261,50.394 129.261,55.499 129.032,55.728 124.115,55.728 122.326,53.939
  Bottom Layer w0.127: RS1.2 69.901,52.708 ; v1(75.692,45.517) D4.2 75.997,47.225 76.505,47.733 76.505,48.565 76.429,48.641 74.295,48.641 71.882,48.641 70.942,49.581 70.942,51.667 69.901,52.708 ; D3.2 75.192,53.194 74.752,53.634 C5.1 71.563,53.634 70.637,52.708 69.901,52.708 ; v1(79.934,38.252) 95.275,38.252 P2.2
CC1: C5.2 D3.1 IC1.15 P1.A5 | length 23.1
  Top Layer w0.127: P1.A5 75.957,51.804 76.199,51.562 v1(76.327,51.562) ; IC1.15 85.213,47.346 85.467,47.6 86.817,47.6 v1(86.893,47.676)
  Bottom Layer w0.127: C5.2 76.149,52.284 ; D3.1 75.692,55.194 75.921,54.966 76.149,54.737 76.149,52.284 ; v1(76.327,51.562) 76.236,51.653 76.236,52.017 76.149,52.104 76.149,52.284 ; v1(86.893,47.676) 84.861,47.676 80.253,52.284 76.149,52.284
CC2: C6.2 D4.1 IC1.14 P1.B5 | length 21.9
  Top Layer w0.127: v1(72.009,49.991) 72.009,50.224 72.339,50.554 P1.B5 ; IC1.14 85.713,47.295 86.528,47.295 86.706,47.117 87.33,47.117 87.394,47.181 87.831,47.181 v1(87.884,47.233)
  Bottom Layer w0.127: v1(72.009,49.991) 74.295,49.991 74.752,49.991 75.194,49.549 D4.1 75.692,49.058 77.586,49.058 79.418,47.227 83.795,47.227 84.463,46.558 87.224,46.558 87.884,47.219 v1(87.884,47.233)
CSP: IC1.19 P1.A1 P1.A12 P1.B1 P1.B12 R21.1 RS1.1 | length 87
  Top Layer w0.127: v1(70.442,48.554) 72.198,48.554 ; P1.A12 74.295,48.304 74.187,48.412 72.794,48.412 P1.B1 72.198,48.554 ; P1.A1 73.628,53.804 73.378,54.054 P1.B12 72.339,54.054 71.501,53.216 71.501,49.251 72.198,48.554 ; IC1.19 82.728,45.954 82.728,46.126 83.083,46.482 v1(83.134,46.482) ; v1(108.625,43.068) R21.1
  Bottom Layer w0.127: RS1.1 69.088,49.908 v1(70.442,48.554) 71.12,47.876 71.12,46.101 73.533,43.688 80.256,43.688 ; v1(83.134,46.482) 83.05,46.482 80.256,43.688 ; v1(108.625,43.068) 106.528,40.97 102.54,40.97 100.33,38.76 98.323,38.76 98.323,41.453 97.485,42.291 94.005,42.291 93.574,41.859 93.574,41.453 93.853,41.173 94.285,41.173 95.225,40.234 95.225,39.294 94.691,38.76 78.461,38.76 74.346,42.875 79.443,42.875 80.256,43.688
DM0: IC1.16 P1.A7 P1.B7 | length 29.7
  Top Layer w0.127: v1(72.009,50.927) 72.009,51.224 72.339,51.554 P1.B7 ; P1.A7 75.129,50.804 v1(76.378,49.555) ; v1(84.099,49.403) 84.379,49.124 84.379,47.781 84.713,47.447 IC1.16
  Bottom Layer w0.127: v1(72.009,50.927) 75.768,50.927 ; v1(76.378,49.555) 76.378,50.317 75.768,50.927 ; v1(84.099,49.403) 85.903,49.403 87.401,47.904 87.401,47.346 87.173,47.117 84.496,47.117 84.133,47.481 81.653,47.481 78.207,50.927 75.768,50.927
DP0: IC1.17 P1.A6 P1.B6 | length 16.2
  Top Layer w0.127: P1.B6 73.664,51.054 73.914,51.304 P1.A6 75.59,51.304 78.842,48.053 78.842,47.498 79.045,47.295 81.813,47.295 81.813,48.057 82.525,48.768 83.642,48.768 84.049,48.362 84.049,47.434 IC1.17
FB: IC1.20 R20.1 | length 20.7
  Top Layer w0.127: v1(82.397,46.685) 82.397,45.613 82.557,45.454 IC1.20 ; R20.1 94.361,48.006 94.615,47.752 v1(94.615,43.485)
  Bottom Layer w0.127: v1(82.397,46.685) 82.685,46.973 83.625,46.973 87.112,43.485 v1(94.615,43.485)
IMON: C36.1 R29.2 | length 4.9
  Top Layer w0.127: R29.2 113.25,42.968 114.173,43.891 C36.1
INT: IC1.10 R30.2 U2.5 | length 22.6
  Top Layer w0.127: IC1.10 87.049,44.867 87.382,44.867 87.554,44.696 87.96,44.696 88.247,44.983 88.247,45.722 v1(88.24,45.73) ; R30.2 103.683,48.652 v1(103.683,49.479) 104.132,49.928 U2.5
  Bottom Layer w0.127: v1(88.24,45.73) 90.191,45.73 90.455,45.466 92.278,45.466 93.116,46.304 101.194,46.304 101.6,46.711 101.6,47.396 v1(103.683,49.479)
"LDO OUT": C1.2 C3.2 D2.2 IC3.6 R2.2 | length 20
  Top Layer w0.127: D2.2 121.971,45.212 122.606,44.577 C1.2 ; R2.2 123.749,47.219 124.384,46.584 124.384,45.695 123.66,44.971 C1.2 ; C3.2 125.186,51.597 IC3.6 125.984,51.323 126.187,51.12 126.187,44.298 125.781,43.891 123.863,43.891 123.66,44.094 C1.2
NetC1_1: C1.1 IC3.4 R2.1 R4.2 | length 5.7
  Top Layer w0.127: C1.1 125.26,45.237 125.095,45.402 R4.2 125.095,46.787 125.349,47.041 R2.1 125.349,48.819 125.46,48.93 IC3.4
NetC7_1: C7.1 U2.23 | length 10.8
  Top Layer w0.127: v1(102.225,55.956) 102.632,55.55 U2.23 ; v1(109.728,57.607) C7.1
  Bottom Layer w0.127: v1(102.225,55.956) 104.416,55.956 104.669,56.209 108.33,56.209 v1(109.728,57.607)
NetC7_2: C7.2 R7.2 | length 3.8
  Top Layer w0.127: C7.2 108.966,60.694 108.966,61.874 109.728,62.636 R7.2
NetC8_1: C8.1 U2.17 | length 17.6
  Top Layer w0.127: U2.17 105.632,55.162 v1(105.639,55.169) ; v1(118.237,57.734) C8.1
  Bottom Layer w0.127: v1(105.639,55.169) 107.383,55.169 110.134,52.418 112.92,52.418 v1(118.237,57.734)
NetC8_2: C8.2 R8.2 | length 1.4
  Top Layer w0.127: C8.2 R8.2
NetC9_2: C9.2 C10.2 C11.2 R9.1 R12.2 R13.2 U2.18 | length 53.8
  Top Layer w0.127: v1(105.131,51.994) v1(105.131,51.994) U2.18 ; C11.2 105.41,61.138 C10.2 105.409,59.056 105.791,58.674 C9.2 107.747,57.833 108.912,56.667 v1@114.643,56.667 ; R9.1 v1@114.643,56.667 ; v1(114.656,56.667) v1@114.643,56.667 ; R12.2 v1(123.199,61.84) ; R13.2 v1(127.39,61.84)
  Bottom Layer w0.127: v1(105.131,51.994) 105.131,55.448 105.342,55.659 107.942,55.659 110.287,53.315 110.287,52.926 110.541,52.672 111.269,52.672 114.656,56.058 v1(114.656,56.667) 119.828,61.84 v1(123.199,61.84) v1(127.39,61.84)
NetC30_1: C30.1 R23.2 | length 1.6
  Top Layer w0.127: R23.2 79.579,45.574 79.839,45.314 C30.1
NetC31_1: C31.1 C34.2 IC1.24 | length 5.4
  Top Layer w0.127: C31.1 81.179,40.132 81.094,40.217 C34.2 82.169,42.35 82.169,43.124 82.499,43.454 IC1.24
NetD5_1: D5.1 R25.2 U2.4 | length 16.9
  Top Layer w0.127: D5.1 97.409,43.129 98.273,42.266 99.238,42.266 100.144,43.172 100.144,48.43 100.381,48.666 100.952,48.666 101.358,48.552 ; v1(100.952,48.958) 101.358,48.552 ; R25.2 101.358,48.552 ; U2.4 v1(103.632,51.46)
  Bottom Layer w0.127: v1(100.952,48.958) 103.454,51.46 v1(103.632,51.46)
NetD6_1: D6.1 R24.2 U2.3 | length 16.2
  Top Layer w0.127: v1(95.402,45.695) 95.415,45.707 R24.2 ; v1(99.314,43.18) D6.1 99.314,45.187 99.89,45.763 99.89,48.958 100.47,49.538 102.682,49.538 103.132,49.987 U2.3
  Bottom Layer w0.127: v1(95.402,45.695) 96.799,45.695 v1(99.314,43.18)
NetIC1_11: IC1.11 R6.2 | length 9.4
  Top Layer w0.127: IC1.11 87.757,45.454 v1(87.757,45.187) ; R6.2 90.932,47.93 90.932,45.974 v1(92.05,44.856)
  Bottom Layer w0.127: v1(87.757,45.187) 88.087,44.856 v1(92.05,44.856)
NetIC1_21: IC1.21 R23.1 | length 2.7
  Top Layer w0.127: R23.1 81.179,45.583 81.514,45.583 82.143,44.954 IC1.21
NetIC3_2: IC3.2 R1.2 R3.2 | length 10.1
  Top Layer w0.127: v1(118.745,55.499) 118.745,54.14 R1.2 ; v1(120.345,51.562) R3.2@121.234,50.673 ; R3.2 R3.2@121.234,50.673 ; IC3.2 122.225,50.673 R3.2@121.234,50.673
  Bottom Layer w0.127: v1(118.745,55.499) 118.745,54.638 119.456,53.927 119.86,53.927 120.345,53.442 v1(120.345,51.562)
NetJP2_3: JP2.3 R29.1 | length 9.6
  Top Layer w0.127: v1(111.252,40.538) R29.1
  Bottom Layer w0.127: v1(111.252,40.538) 118.643,40.538 JP2.3
NetLED1_2: LED1.2 R21.2 | length 7.7
  Top Layer w0.127: R21.2 110.084,41.768 110.084,44.602 109.728,44.958 109.728,47.61 109.931,47.813 LED1.2
NetM1_4: M1.4 M2.4 R14.2 | length 6.8
  Top Layer w0.127: R14.2 85.486,52.73 85.699,52.943 85.699,53.163 ; M1.4 85.699,53.163 ; M2.4 89.789,53.238 89.459,52.908 85.954,52.908 85.699,53.163
NetR26_1: R26.1 RNTC1.2 | length 4.9
  Top Layer w0.127: v1(105.791,41.834) RNTC1.2 ; v1(107.823,44.221) R26.1
  Bottom Layer w0.127: v1(105.791,41.834) 105.791,42.189 v1(107.823,44.221)
NTC: R22.2 R26.2 U2.9 | length 5.4
  Top Layer w0.127: U2.9 106.481,51.079 107.584,49.977 R22.2 107.584,47.483 107.823,47.244 R26.2
S_CLK: IC1.8 P2.4 | length 11.6
  Top Layer w0.127: IC1.8 87.262,43.954 88.341,42.875 89.713,42.875 89.713,44.45 90.018,44.755 91.288,44.755 91.694,44.348 P2.4
S_DAT: IC1.7 P2.5 | length 4.9
  Top Layer w0.127: IC1.7 87.381,43.454 89.154,41.681 P2.5
SCL: IC1.13 JP3.3 R25.1 | length 25.1
  Top Layer w0.127: IC1.13 86.213,46.812 87.612,46.812 87.681,46.743 88.78,46.743 89.179,47.142 v1(89.179,47.803) ; v1(100.838,46.965) 100.851,46.952 R25.1@101.473,46.952 ; R25.1 R25.1@101.473,46.952 ; JP3.3 101.473,41.656 R25.1@101.473,46.952
  Bottom Layer w0.127: v1(89.179,47.803) 96.215,47.803 97.053,46.965 v1(100.838,46.965)
SDA: IC1.12 JP3.1 R24.1 | length 30.9
  Top Layer w0.127: IC1.12 87.534,45.954 87.734,46.154 v1(87.734,46.252) ; v1(91.491,46.609) R24.1 93.815,42.164 v1(94.221,41.758)
  Bottom Layer w0.127: v1(87.734,46.252) 88.091,46.609 v1(91.491,46.609) ; v1(94.221,41.758) 96.926,41.758 98.044,40.64 98.044,37.641 98.118,37.567 106.528,37.567 JP3.1
SRN: C18.2 R16.2 U2.14 | length 9
  Top Layer w0.127: U2.14 107.143,53.194 108.534,54.585 112.305,54.585 C18.2 113.69,53.987 113.805,54.102 R16.2
SRP: C18.1 R9.2 U2.15 | length 11.5
  Top Layer w0.127: U2.15 106.481,54.458 106.913,54.889 112.305,54.889 C18.1 113.399,54.991 115.062,54.991 115.824,55.753 R9.2
SW1: L1.1 R7.1 U2.21 | length 16.4
  Top Layer w0.127: v1(103.302,56.54) 103.632,56.21 U2.21 ; R7.1 110.338,61.468 ; v1(110.617,60.249) 110.617,61.189 110.338,61.468 ; L1.1 111.506,60.579 110.617,61.468 110.338,61.468
  Bottom Layer w0.127: v1(103.302,56.54) 107.01,60.249 v1(110.617,60.249)
SW2: L1.2 R8.1 U2.19 | length 21.8
  Top Layer w0.127: U2.19 104.632,56.549 v1(104.877,56.794) ; v1(115.392,63.03) v1@115.61,63.03 ; L1.2 115.394,62.814 v1@115.61,63.03 ; R8.1 v1@115.61,63.03
  Bottom Layer w0.127: v1(104.877,56.794) 106.248,58.166 110.528,58.166 v1(115.392,63.03)
T/I: JP2.2 U2.7 | length 18
  Top Layer w0.127: U2.7 105.132,49.962 105.334,49.76 105.334,46.457 v1(105.512,46.279)
  Bottom Layer w0.127: v1(105.512,46.279) 112.344,46.279 JP2.2
TO_ACGATE: M1.1 M1.2 M1.3 M2.1 M2.2 M2.3 R14.1 U2.27 | length 27.3
  Top Layer w0.127: M1.1 M1.2 ; R14.1 84.186,52.73 84.379,52.923 M1.2 ; v1(87.071,56.617) 87.071,55.194 87.757,54.508 ; M2.3 M2.2 M2.1 87.809,54.456 87.757,54.508 ; v1(100.914,52.774) 100.954,52.734 101.754,52.734 U2.27 ; M1.2 M1.3 85.039,54.254 85.293,54.508 87.757,54.508
  Bottom Layer w0.127: v1(87.071,56.617) 96.991,56.617 100.834,52.774 v1(100.914,52.774)
TO_ADP: C4.1 C22.2 J3.2 M1.5 M1.6 M1.7 M1.8 P1.A4 P1.A9 P1.B4 P1.B9 R5.2 U2.28 | length 90
  Top Layer w0.3: P1.B4 73.508,50.054 73.758,49.804 74.886,49.804 75.121,49.569 75.121,48.039 75.057,47.975 75.057,46.228 74.397,45.568 70.714,45.568 69.418,46.863 69.418,55.27 70.663,56.515 73.457,56.515 75.311,54.661 75.311,52.304 ; P1.B9 73.508,52.554 73.758,52.304 P1.A4 75.311,52.304 ; R5.2 79.579,49.159 80.119,49.699 ; J3.2 83.719,58.283 M1.8 M1.7 M1.6 M1.5 ; M1.8@83.719,56.641 83.477,56.641 83.058,56.222 83.058,51.46 84.471,50.047 ; C22.2 86.704,49.982 86.639,50.047 C4.1 84.471,50.047 ; v1(99.695,52.527) 100.028,52.194 U2.28 ; 75.311,52.304 77.514,52.304 80.119,49.699 ; 80.119,49.699 80.467,50.047 84.471,50.047
  Bottom Layer w0.3: J3.2 83.379,58.623 95.979,58.623 101.727,52.875 101.727,52.373 101.551,52.197 100.025,52.197 v1(99.695,52.527)
TO_FB: R17.1 R18.2 R20.2 U2.29 | length 18.8
  Top Layer w0.127: v1(92.812,49.225) 93.838,50.252 R17.1 v1(93.015,50.8) ; R18.2 R18.2@95.265,49.022 ; R20.2 95.415,48.565 95.265,48.715 R18.2@95.265,49.022 ; v1(95.961,49.022) R18.2@95.265,49.022 ; v1(100.584,51.287) 100.99,51.694 U2.29
  Bottom Layer w0.127: v1(92.812,49.225) 94.082,49.225 ; v1(93.015,50.8) 93.015,50.292 94.082,49.225 ; v1(95.961,49.022) 94.285,49.022 94.082,49.225 ; v1(100.584,51.287) 98.522,49.225 94.082,49.225
TO_IAN: C13.1 C14.1 R11.2 U2.24 | length 35.3
  Top Layer w0.127: R11.2 93.788,55.434 94.488,56.134 94.488,61.036 94.691,61.239 96.317,61.239 96.596,60.96 96.596,56.286 97.536,55.347 97.664,55.347 C14.1 ; v1(100.559,55.245) 100.052,55.245 C14.1 ; U2.24 99.317,53.694 C14.1 ; v1(110.998,53.162) C13.1
  Bottom Layer w0.127: v1(100.559,55.245) 104.437,55.245 105.105,55.913 108.247,55.913 v1(110.998,53.162)
TO_IAP: C12.1 C14.2 R10.2 U2.26 | length 26
  Top Layer w0.127: R10.2 93.788,51.957 94.082,51.664 v1(94.513,51.664) ; v1(96.647,52.832) 96.994,53.179 97.324,53.179 v1(97.409,53.264) C14.2 98.247,53.264 101.117,53.264 101.188,53.194 U2.26 ; v1(107.989,52.756) C12.1
  Bottom Layer w0.127: v1(94.513,51.664) 95.809,51.664 v1@96.812,52.667 ; v1(96.647,52.832) v1@96.812,52.667 ; v1(97.409,53.264) v1@96.812,52.667 ; v1(107.989,52.756) 107.417,52.756 105.867,51.206 105.156,51.206 104.394,51.968 102.438,51.968 102.286,51.816 97.663,51.816 v1@96.812,52.667
TO_VIN: C19.1 C20.1 C21.1 R11.1 R15.1 R32.1 U2.22 | length 62.1
  Top Layer w0.127: R15.1 v1(93.463,61.519) ; v1(95.377,55.042) 95.388,55.031 R11.1 ; v1(97.663,61.595) R32.1 97.663,55.905 100.922,55.905 103.469,58.453 103.469,59.142 ; U2.22 103.132,55.428 102.809,55.75 102.809,57.01 103.632,57.833 C19.1 104.013,58.598 103.469,59.142 ; C21.1 103.505,61.148 103.469,61.112 C20.1 103.469,59.142
  Bottom Layer w0.127: v1(95.377,55.042) 83.998,55.042 81.077,57.963 81.077,60.452 82.093,61.468 93.412,61.468 v1(93.463,61.519) 97.587,61.519 v1(97.663,61.595)
TP_VBUS: C16.2 C17.2 J3.1 M2.5 M2.6 M2.7 M2.8 R6.1 R10.1 R15.2 R17.2 R32.2 | length 71
  Top Layer w0.127: J3.1 84.657,60.797 86.639,60.797 ; M2.5 M2.6 M2.7 M2.8 87.809,57.454 86.639,58.623 86.639,60.797 ; R6.1 90.888,49.867 90.985,49.867 91.142,50.024 91.142,60.201 90.985,60.358 90.736,60.358 C17.2 C16.2 86.639,60.797 ; R17.2 95.392,52.147 95.388,52.147 R10.1 95.388,52.934 94.956,53.365 ; R15.2 95.513,56.702 94.717,55.905 94.717,53.605 94.956,53.365 ; v1(99.695,61.595) v1@99.713,61.577 ; R32.2 v1@99.713,61.577 ; 94.956,53.365 93.066,53.365 92.608,53.823 92.608,61.392 93.65,62.433 99.162,62.433 99.713,61.882 v1@99.713,61.577
  Bottom Layer w0.127: J3.1 98.171,60.071 v1(99.695,61.595)
TS: JP2.1 R27.1 R31.2 | length 21.7
  Top Layer w0.127: R31.2 102.489,44.069 103.251,43.307 104.369,43.307 105.054,43.993 ; R27.1 105.69,44.628 105.054,43.993 ; JP2.1 110.896,37.871 106.197,37.871 105.054,39.014 105.054,43.993
VBATT: C2.1 C27.1 C28.1 C29.1 IC3.1 J2.2 R1.1 R12.1 R13.1 R16.1 U2.12 | length 71.2
  Top Layer w0.3: U2.12 107.267,52.194 v1(107.671,51.791) ; C27.1 C28.1 v1(114.554,50.355) C29.1 ; R16.1 117.221,54.102 118.547,52.776 118.547,52.663 118.797,52.413 119.873,52.413 ; IC3.1 122.524,51.323 122.382,51.181 v1(122.301,51.181) 122.244,51.238 122.244,51.679 121.436,52.487 119.947,52.487 119.873,52.413 ; R13.1 125.34,62.586 124.527,63.398 121.962,63.398 121.149,62.586 R12.1 120.049,58.928 119.873,58.752 119.873,52.413
  Bottom Layer w0.3: v1(107.671,51.791) 108.534,50.927 120.709,50.927 121.312,51.53 121.871,51.53 122.22,51.181 122.382,51.181 122.731,51.53 J2.2 127.222,50.355 v1(114.554,50.355)
VBUS_IN_DSG: IC1.18 R5.1 | length 5.6
  Top Layer w0.127: R5.1 v1(81.179,49.302) ; v1(83.312,48.235) 83.713,47.834 IC1.18
  Bottom Layer w0.127: v1(81.179,49.302) 82.245,49.302 v1(83.312,48.235)
VCC: C35.1 R30.1 U2.1 | length 9.8
  Top Layer w0.127: C35.1 98.881,48.16 v1(98.882,48.158) ; v1(100.635,48.158) 100.889,47.904 102.089,47.904 102.641,47.352 R30.1 ; v1(101.387,50.47) 101.793,50.876 U2.1
  Bottom Layer w0.127: v1(100.635,48.158) v1(98.882,48.158) 101.194,50.47 v1(101.387,50.47)
"VDD MCU": C32.1 C33.2 D1.1 D2.1 IC1.23 | length 59.9
  Top Layer w0.127: IC1.23 81.445,43.954 81.179,43.688 C33.2 81.179,42.52 80.543,42.52 80.416,42.393 80.416,40.386 80.442,40.361 80.442,38.608 80.848,38.202 89.874,38.202 90.687,39.014 ; C32.1 90.687,39.014 ; D1.1 D2.1 117.043,45.212 116.103,44.272 116.103,39.853 113.462,37.211 91.934,37.211 90.687,38.458 90.687,39.014
VNTC: R22.1 R27.2 U2.8 | length 4.7
  Top Layer w0.127: U2.8 105.632,49.069 106.284,48.417 R22.1 106.284,47.361 106.426,47.219 R27.2
VTARG: D1.2 P2.1 | length 27.3
  Top Layer w0.127: D1.2 v1(120.955,48.666)
  Bottom Layer w0.127: P2.1 99.314,41.58 106.401,48.666 v1(120.955,48.666)
XRES: C26.2 IC1.9 P2.3 | length 16.6
  Top Layer w0.127: IC1.9 86.975,44.442 v1@87.765,44.442 ; v1(87.765,44.206) v1@87.765,44.442 ; C26.2 89.095,45.436 88.101,44.442 v1@87.765,44.442
  Bottom Layer w0.127: v1(87.765,44.206) 87.855,44.115 88.222,44.115 88.319,44.018 94.894,44.018 95.123,43.79 95.123,43.155 94.691,42.723 93.777,42.723 93.32,42.266 93.32,40.665 P2.3
pads on no net: IC1.1 IC1.2 IC1.3 IC1.4 IC1.5 IC1.6 IC1.25 IC3.5 M1.9 M2.9 MP1. MP2. MP3. MP4. P1.A2 P1.A3 P1.A8 P1.A10 P1.A11 P1.B2 P1.B3 P1.B8 P1.B10 P1.B11 P1.MH1 P1.MH2 P1.MH3 P1.MH4 P1.MH5 P1.MH6 U2.13

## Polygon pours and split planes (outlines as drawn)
AGND on Bottom Layer "AGND_L02_P009" (solid, pour order 9): 66.675,57.404 72.263,57.404 72.517,57.658 72.517,63.627 77.089,68.199 126.365,68.199 132.08,62.484 132.08,52.705 104.14,52.705 103.251,53.594 103.251,54.864 99.441,58.674 99.441,59.817 99.06,60.198 86.36,60.198 85.09,61.468 80.264,61.468 80.137,61.595 80.01,61.468 80.01,58.166 80.137,58.166 81.788,56.515 81.915,56.642 94.869,56.642 98.552,52.959 98.552,51.562 105.283,51.562 108.077,48.768 108.331,48.768 108.331,49.276 108.585,49.53 108.712,49.403 127.381,49.403 127.762,49.784 132.08,49.784 132.08,40.767 126.238,34.925 76.708,34.925 71.374,40.259 71.374,44.45 66.929,44.45 66.548,44.831 66.675,44.958
TO_ADP on Bottom Layer "TO_ADP_L02_P005" (solid, pour order 5): 80.391,60.833 85.09,60.833 86.741,59.182 98.679,59.182 98.679,57.912 102.616,53.975 102.616,52.451 102.108,51.943 99.314,51.943 99.314,53.721 95.25,57.785 82.423,57.785 80.391,59.817
VBATT on Bottom Layer "VBATT_L02_P004" (solid, pour order 4): 107.442,52.324 109.093,52.324 109.601,51.816 130.302,51.816 130.302,50.419 129.921,50.038 108.204,50.038 106.68,51.562
AGND on Top Layer "AGND_L01_P008" (solid, pour order 8): 72.136,61.722 72.136,64.516 76.073,68.453 126.111,68.453 131.699,62.865 131.699,39.624 126.873,34.798 75.311,34.798 72.644,37.465 72.644,41.783 74.803,41.783 79.248,46.228 83.566,46.228 83.566,46.736 85.09,48.26 90.297,48.26 90.297,52.07 90.551,52.324 89.027,53.848 88.265,53.848 88.265,57.658 88.392,57.785 82.931,63.246 82.931,63.627 75.184,63.627 73.279,61.722
TO_ADP on Top Layer "TO_ADP_L01_P007" (solid, pour order 7): 68.58,55.499 68.58,46.228 70.104,44.704 75.946,44.704 77.343,46.101 77.343,48.133 77.724,48.133 78.74,47.117 82.296,47.117 82.296,47.752 83.693,49.149 89.281,49.149 89.154,49.022 89.027,49.149 89.027,51.943 87.503,51.943 86.741,52.705 86.741,58.674 83.058,62.357 75.438,62.357

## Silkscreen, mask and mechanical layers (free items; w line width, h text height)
Top Overlay:
  text "VBUSC" at 81.942,61.695 h0.5 r90
  text "VBUS" at 84.355,61.568 h0.5 r90
  text "VBATT" at 130.021,51.154 h0.5
  text "GND" at 130.148,49.249 h0.5
  text "TS" at 114.581,38.862 h0.5 r90
  text "T/I" at 117.248,38.529 h0.5 r90
  text "IMON" at 120.042,37.946 h0.5 r90
  text "SCL" at 103.659,36.287 h0.5 r90
  text "SDA" at 108.993,36.287 h0.5 r90
  text "XRES" at 94.388,36.16 h0.5 r90
  text "AGND" at 97.182,36.16 h0.5 r90
  text "AGND" at 106.199,35.787 h0.5 r90
  text "S_DAT" at 89.479,35.66 h0.5 r90
  text "S_CLK" at 92.019,35.66 h0.5 r90
  text "VTARG" at 99.595,35.66 h0.5 r90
